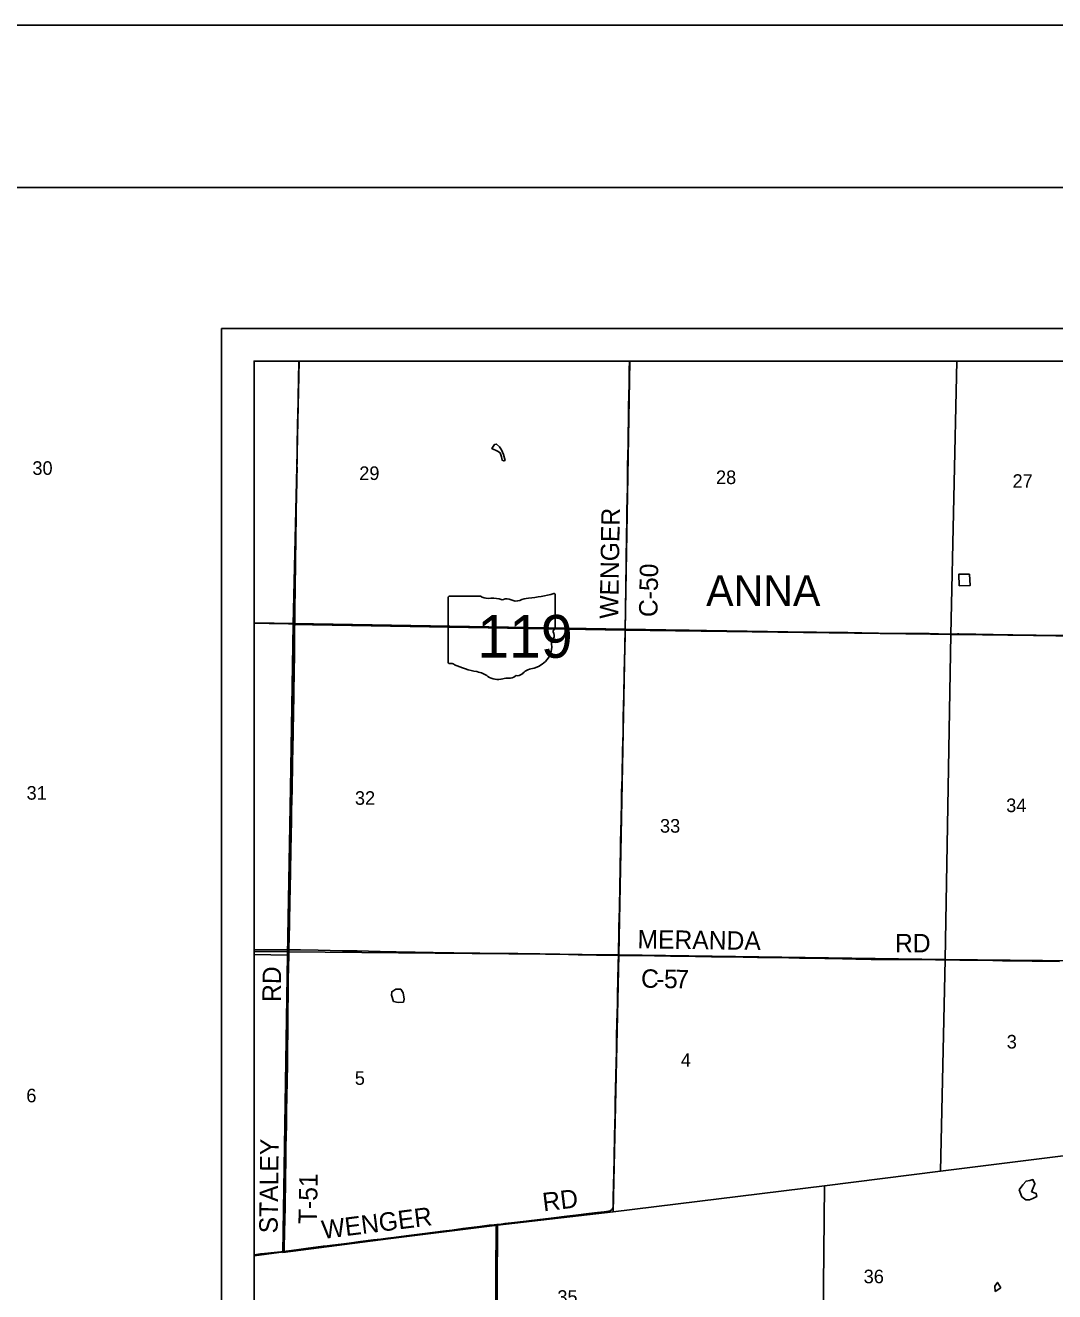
# Model space of a CAD drawing. Extents: x -784 to 1375, y -225 to 440.
# Drawn here: x 430.1 to 493.6, y 362 to 440 of the extents above; entities that cross this region are included whole.
import ezdxf

# ---------------------------------------------------------------- set-up
doc = ezdxf.new("R2010")
doc.units = 0
for name, color, linetype in [('GM_X_Corporation_Text', 7, 'Continuous'), ('GM_X_County_Road', 7, 'Continuous'), ('GM_X_County_Road_Text', 7, 'Continuous'), ('GM_X_Minor_Lake', 7, 'Continuous'), ('GM_X_Section', 7, 'Continuous'), ('GM_X_Section_Text', 7, 'Continuous'), ('GM_X_State_Location', 7, 'Continuous'), ('GM_X_State_Route', 7, 'Continuous'), ('GM_X_State_Shield', 7, 'Continuous'), ('GM_X_Township', 7, 'Continuous'), ('GM_X_Township_Road', 7, 'Continuous'), ('GM_X_Township_Road_Text', 7, 'Continuous'), ('SH_Border', 7, 'Continuous'), ('SH_Cut_Line', 7, 'Continuous'), ('SH_Data', 7, 'Continuous')]:
    doc.layers.add(name, color=color, linetype=linetype)

msp = doc.modelspace()

# ---------------------------------------------------------------- linework, layer by layer
at = {"layer": 'GM_X_County_Road'}
for points in [[(467.114, 402.781), (467.115, 402.882), (467.119, 403.76), (467.119, 404.034), (467.122, 404.171), (467.145, 405.264), (467.173, 407.054), (467.196, 408.546), (467.21, 409.503), (467.219, 410.075), (467.232, 410.87), (467.243, 411.492), (467.251, 411.989), (467.259, 412.834), (467.275, 413.543), (467.285, 414.164), (467.294, 414.947), (467.309, 415.544), (467.319, 416.501), (467.348, 417.881), (467.363, 418.751), (467.375, 419.309)], [(466.693, 382.69), (467.683, 382.675), (468.913, 382.652), (469.895, 382.64), (471.448, 382.616), (472.417, 382.602), (474.381, 382.57), (475.263, 382.557), (475.984, 382.551), (477.189, 382.528), (477.848, 382.522), (478.42, 382.514), (478.855, 382.508), (479.414, 382.498), (480.023, 382.487), (480.508, 382.482), (481.315, 382.457), (482.259, 382.439), (482.768, 382.436), (483.315, 382.43), (483.787, 382.43), (484.57, 382.433), (485.167, 382.432), (485.751, 382.426), (486.223, 382.42), (487.093, 382.412), (487.739, 382.402), (488.472, 382.387), (489.764, 382.373), (490.361, 382.361), (490.709, 382.355), (491.579, 382.346), (492.188, 382.339), (492.921, 382.332), (493.207, 382.328), (493.878, 382.312)]]:
    msp.add_lwpolyline(points, dxfattribs=at)
at = {"layer": 'GM_X_Minor_Lake'}
msp.add_line((489.877, 362.3), (489.902, 361.974), dxfattribs=at)
for points in [[(459.484, 413.84), (459.357, 414.024), (459.185, 414.2), (459.056, 414.179), (458.893, 413.916), (459.247, 413.752), (459.405, 413.651), (459.478, 413.4)], [(459.478, 413.4), (459.536, 413.202), (459.634, 413.155), (459.703, 413.192), (459.601, 413.55), (459.484, 413.84)], [(488.326, 406.186), (487.673, 406.187), (487.686, 405.469)], [(487.686, 405.469), (488.362, 405.48), (488.326, 406.186)], [(453.431, 380.37), (453.273, 380.609), (452.977, 380.605), (452.725, 380.449), (452.699, 380.245), (452.837, 379.85)], [(452.837, 379.85), (453.111, 379.784), (453.445, 379.81), (453.478, 379.992), (453.431, 380.37)], [(492.146, 368.115), (492.354, 368.619), (492.237, 368.871), (492.046, 368.822), (491.809, 368.782), (491.608, 368.551), (491.381, 368.23)], [(491.381, 368.23), (491.557, 367.817), (491.789, 367.631), (492.032, 367.633), (492.224, 367.705), (492.469, 367.829), (492.442, 368.019), (492.146, 368.115)], [(490.262, 362.199), (490.049, 362.532), (489.877, 362.3)], [(489.902, 361.974), (490.262, 362.199)]]:
    msp.add_lwpolyline(points, dxfattribs=at)
at = {"layer": 'GM_X_Section'}
for p, q in [((467.389, 419.309), (447.006, 419.309)), ((487.553, 419.309), (467.389, 419.309)), ((507.516, 419.309), (487.553, 419.309)), ((444.236, 403.181), (444.236, 382.934)), ((444.236, 382.934), (444.236, 364.18)), ((444.236, 364.18), (444.236, 354.38))]:
    msp.add_line(p, q, dxfattribs=at)
for points in [[(447.006, 419.309), (444.236, 419.309), (444.236, 403.181)], [(444.236, 403.181), (446.704, 403.137), (447.006, 419.309)], [(447.006, 419.309), (446.704, 403.137), (467.106, 402.786), (467.389, 419.309)], [(467.389, 419.309), (467.106, 402.786), (487.175, 402.456), (487.553, 419.309)], [(487.553, 419.309), (487.175, 402.456), (507.224, 402.301), (507.516, 419.309)], [(444.236, 382.934), (446.364, 382.916), (446.704, 403.137), (444.236, 403.181)], [(444.236, 364.18), (446.077, 364.411), (446.364, 382.916), (444.236, 382.934)], [(444.236, 354.38), (459.168, 354.279), (459.245, 366.065), (446.077, 364.411), (444.236, 364.18)]]:
    msp.add_lwpolyline(points, dxfattribs=at)
for points in [[(446.704, 403.137), (467.106, 402.786), (466.723, 382.718), (446.364, 382.916)], [(467.106, 402.786), (487.175, 402.456), (486.823, 382.433), (466.723, 382.718)], [(487.175, 402.456), (507.224, 402.301), (506.818, 382.234), (486.823, 382.433)], [(446.364, 382.916), (466.723, 382.718), (466.358, 366.879), (459.245, 366.065), (446.077, 364.411)], [(466.723, 382.718), (486.823, 382.433), (486.548, 369.394), (479.388, 368.483), (466.358, 366.879)], [(486.823, 382.433), (506.818, 382.234), (506.617, 371.896), (499.684, 371.026), (486.548, 369.394)], [(499.684, 371.026), (499.42, 354.13), (479.771, 354.211), (479.249, 354.244), (479.388, 368.483), (486.548, 369.394)], [(466.358, 366.879), (479.388, 368.483), (479.249, 354.244), (459.168, 354.279), (459.245, 366.065)]]:
    msp.add_lwpolyline(points, close=True, dxfattribs=at)
at = {"layer": 'GM_X_State_Route'}
for points in [[(444.236, 403.166), (444.292, 403.165), (445.162, 403.148), (445.933, 403.132), (446.367, 403.125), (446.609, 403.125), (446.745, 403.125), (447.771, 403.096), (448.703, 403.082), (449.56, 403.073), (450.679, 403.05), (451.473, 403.037), (452.43, 403.023), (454.593, 402.988), (456.196, 402.961), (457.637, 402.935), (458.296, 402.926), (459.463, 402.906), (461.663, 402.874), (462.396, 402.862), (463.751, 402.838), (464.558, 402.828), (466.559, 402.789), (467.114, 402.781), (468.137, 402.768), (471.057, 402.719), (472.213, 402.697), (474.151, 402.665), (476.189, 402.632), (477.915, 402.605)], [(477.915, 402.605), (478.9, 402.596), (479.658, 402.585), (480.428, 402.579), (480.838, 402.575), (481.695, 402.563), (482.727, 402.553), (484.155, 402.531), (485.843, 402.516), (486.418, 402.501), (487.127, 402.489)], [(487.127, 402.489), (487.581, 402.494), (487.667, 402.492)], [(487.667, 402.492), (489.792, 402.455), (490.867, 402.437)], [(490.867, 402.437), (490.996, 402.434), (491.754, 402.427), (492.087, 402.425)], [(492.087, 402.425), (492.167, 402.425), (492.437, 402.421), (493.682, 402.405), (494.114, 402.398), (495.239, 402.389), (495.282, 402.388), (495.555, 402.385), (495.682, 402.384)]]:
    msp.add_lwpolyline(points, dxfattribs=at)
at = {"layer": 'GM_X_State_Shield'}
for p, q in [((456.199, 404.746), (456.199, 400.744)), ((458.194, 404.815), (456.264, 404.815)), ((462.791, 402.821), (462.791, 404.914)), ((462.79, 402.821), (462.791, 402.821))]:
    msp.add_line(p, q, dxfattribs=at)
for centre, major_axis, start_param, end_param in [((456.274, 404.755), (0.0764, 0), 1.712693, 3.28349), ((458.654, 405.28), (0.741, 0), 4.042523, 4.731795), ((458.899, 402.568), (2.659, 0), 1.404758, 1.657858), ((459.503, 404.776), (0.214, 0), 3.836095, 5.185415), ((459.817, 404.313), (0.444, 0), 0.950623, 2.079405), ((460.39, 404.948), (0.534, 0), 4.081561, 5.145723), ((461.334, 403.593), (1.406, 0), 1.699011, 2.107814), ((460.442, 410.272), (6.99, 0), 4.814394, 5.042369), ((462.717, 404.923), (0.0734, 0), 6.141152, 7.989035), ((462.774, 402.667), (0.114, 0), 1.883978, 3.671073), ((462.712, 402.813), (0.0785, 0), 5.05454, 6.418171), ((460.834, 401.678), (1.748, 0), 5.101752, 6.440018), ((463.053, 401.944), (0.496, 0), 2.387724, 3.262537), ((462.051, 402.402), (0.682, 0), 5.934695, 6.695948), ((456.275, 400.735), (0.077, 0), 3.00124, 4.508301), ((456.287, 401.145), (0.588, 0), 4.665946, 4.897461), ((456.407, 400.513), (0.212, 0), 0.519207, 1.627899), ((459.084, 404.109), (5.048, 0), 4.195997, 4.488961), ((461.571, 399.62), (0.958, 0), 1.647645, 2.488434), ((457.579, 398.946), (1.579, 0), 0.823519, 1.323587), ((459.287, 400.493), (1.002, 0), 4.026481, 4.996735), ((459.866, 399.109), (0.824, 0), 1.495662, 1.94098), ((459.939, 400.193), (0.534, 0), 4.691044, 5.507374), ((460.422, 399.806), (0.15, 0), 1.147584, 2.315152), ((460.358, 400.356), (0.565, 0), 4.937069, 5.64225)]:
    msp.add_ellipse(centre, major_axis=major_axis, ratio=0.8, start_param=start_param, end_param=end_param, dxfattribs=at)
at = {"layer": 'GM_X_Township'}
msp.add_line((567.763, 419.309), (447.025, 419.309), dxfattribs=at)
for points in [[(447.025, 419.309), (444.236, 419.309), (444.236, 382.734)], [(444.236, 382.734), (446.293, 382.704), (446.474, 392.987), (446.652, 403.07), (446.855, 411.89), (447.025, 419.309)], [(447.025, 419.309), (446.855, 411.89), (446.652, 403.07), (467.059, 402.728), (492.276, 402.408), (492.603, 402.404), (493.649, 402.379), (495.222, 402.342), (497.28, 402.294), (498.869, 402.289), (499.79, 402.287), (508.769, 402.226), (510.045, 402.212), (511.496, 402.178), (514.371, 402.111), (537.416, 401.801), (552.453, 401.662), (567.523, 401.722), (567.763, 419.309)], [(459.121, 359.929), (459.158, 366.091), (446.019, 364.376), (446.293, 382.704), (446.474, 392.987), (446.652, 403.07), (467.059, 402.728), (492.276, 402.408), (492.603, 402.404), (493.649, 402.379)], [(444.236, 382.734), (444.236, 283.309), (458.267, 283.309)], [(458.267, 283.309), (458.263, 284.231), (458.296, 294.134), (458.336, 314.323), (458.289, 334.394), (458.283, 337.182), (458.257, 342.903), (458.257, 344.192), (458.276, 344.705), (458.316, 345.264), (458.426, 346.547), (458.496, 347.13), (458.717, 349.506), (458.868, 351.4), (458.971, 352.658), (459.085, 354.3), (459.121, 359.929), (459.158, 366.091), (446.019, 364.376), (446.293, 382.704), (444.236, 382.734)]]:
    msp.add_lwpolyline(points, dxfattribs=at)
at = {"layer": 'GM_X_Township_Road'}
for points in [[(446.872, 411.883), (446.879, 412.233), (446.884, 412.593), (446.882, 412.979), (446.888, 413.562), (446.896, 414.134), (446.899, 414.407), (446.91, 415.003), (446.923, 415.45), (446.933, 416.047), (446.951, 416.842), (446.965, 417.414), (446.973, 417.836), (446.993, 418.643), (447.004, 419.166), (447.006, 419.309)], [(446.745, 403.125), (446.746, 403.187), (446.751, 403.709), (446.758, 404.33), (446.766, 405.001), (446.781, 405.809), (446.784, 406.405), (446.798, 407.337), (446.808, 407.983), (446.822, 408.728), (446.832, 409.449), (446.839, 410.095), (446.853, 410.978), (446.872, 411.883)], [(446.578, 392.987), (446.588, 393.434), (446.599, 393.993), (446.607, 394.441), (446.613, 394.689), (446.624, 395.36), (446.644, 396.478), (446.665, 397.634), (446.681, 398.665), (446.694, 399.274), (446.704, 399.771), (446.712, 400.342), (446.72, 401.026), (446.726, 401.473), (446.733, 402.044), (446.734, 402.553), (446.738, 402.864), (446.745, 403.125)], [(466.693, 382.69), (466.7, 383.133), (466.713, 383.816), (466.722, 384.45), (466.748, 385.593), (466.774, 386.997), (466.796, 387.979), (466.808, 388.488), (466.818, 388.948), (466.828, 389.631), (466.845, 390.414), (466.857, 391.023), (466.88, 392.203), (466.888, 392.75), (466.901, 393.172), (466.916, 393.644), (466.924, 394.203), (466.938, 394.812), (466.949, 395.296), (466.962, 395.856), (466.974, 396.402), (466.982, 396.899), (466.99, 397.284), (467.009, 398.117), (467.023, 398.738), (467.053, 400.055), (467.07, 400.912), (467.089, 401.571), (467.107, 402.428), (467.114, 402.781)], [(446.38, 383.029), (446.384, 383.196), (446.395, 383.73), (446.413, 384.7), (446.445, 386.041), (446.46, 386.774), (446.483, 387.88), (446.505, 389.172), (446.521, 390.092), (446.537, 390.949), (446.55, 391.62), (446.576, 392.9), (446.578, 392.987)], [(444.236, 383.037), (444.99, 383.035), (445.711, 383.035), (446.27, 383.03), (446.38, 383.029)], [(446.242, 372.949), (446.245, 373.082), (446.262, 374.001), (446.284, 374.908), (446.285, 375.182), (446.296, 375.716), (446.296, 376.425), (446.302, 377.182), (446.311, 377.766), (446.318, 378.661), (446.322, 379.233), (446.333, 380.314), (446.339, 380.699), (446.345, 381.159), (446.358, 382.003), (446.371, 382.649), (446.38, 383.029)], [(446.38, 383.029), (447.091, 383.021), (448.184, 383.002), (448.918, 382.991), (449.688, 382.976), (450.583, 382.961), (451.291, 382.951), (452.012, 382.935), (452.994, 382.909), (453.677, 382.893), (454.162, 382.883), (454.572, 382.873), (455.267, 382.858), (456.15, 382.843), (456.547, 382.838), (456.994, 382.833), (457.591, 382.827), (458.15, 382.822), (459.02, 382.811), (460.487, 382.793), (461.842, 382.774), (463.072, 382.753), (463.607, 382.741), (464.203, 382.725), (464.998, 382.713), (465.346, 382.709), (465.905, 382.705), (466.489, 382.693), (466.564, 382.692), (466.693, 382.69)], [(459.189, 366.105), (459.464, 366.131), (459.698, 366.158), (460.105, 366.207), (461.007, 366.313), (461.846, 366.41), (462.549, 366.499), (463.511, 366.615), (464.065, 366.687), (464.868, 366.781), (465.399, 366.843), (465.818, 366.891), (466.077, 366.92), (466.148, 366.935), (466.203, 366.956), (466.244, 366.979), (466.281, 367.008), (466.311, 367.042), (466.335, 367.081), (466.354, 367.136), (466.366, 367.206), (466.371, 367.304), (466.375, 367.814), (466.382, 368.51), (466.401, 369.317), (466.419, 370.125), (466.432, 370.647), (466.444, 371.131), (466.452, 371.665), (466.462, 372.2), (466.483, 372.995), (466.5, 373.715), (466.512, 374.374), (466.537, 375.368), (466.551, 376.026), (466.564, 376.846), (466.582, 377.667), (466.602, 378.549), (466.626, 379.691), (466.638, 380.35), (466.654, 381.108), (466.683, 382.238), (466.693, 382.661), (466.693, 382.69)], [(446.091, 364.449), (446.094, 364.534), (446.098, 364.646), (446.121, 365.64), (446.135, 366.41), (446.145, 367.18), (446.156, 367.603), (446.172, 368.485), (446.184, 369.094), (446.196, 369.976), (446.198, 370.324), (446.203, 370.982), (446.21, 371.454), (446.227, 372.324), (446.242, 372.949)], [(448.75, 364.79), (449.069, 364.83), (449.6, 364.896), (450.105, 364.96), (450.795, 365.049), (451.597, 365.149), (452.04, 365.206), (452.484, 365.263), (452.854, 365.309), (453.607, 365.4), (454.592, 365.528), (455.875, 365.692), (456.442, 365.763), (457.107, 365.849), (458.155, 365.986), (458.734, 366.058), (459.031, 366.09), (459.189, 366.105)], [(459.122, 354.347), (459.133, 354.603), (459.139, 354.988), (459.143, 356.056), (459.148, 357.237), (459.152, 358.169), (459.154, 359.251), (459.16, 359.922), (459.163, 360.581), (459.167, 361.326), (459.167, 362.122), (459.171, 362.719), (459.175, 363.539), (459.176, 364.247), (459.178, 364.956), (459.177, 365.615), (459.185, 365.938), (459.189, 366.105)], [(444.236, 364.243), (444.382, 364.26), (444.629, 364.288), (444.888, 364.318), (445.469, 364.379), (446.091, 364.449)], [(446.091, 364.449), (446.21, 364.463), (446.863, 364.547), (447.418, 364.616), (447.579, 364.638)], [(447.579, 364.638), (448.49, 364.758), (448.75, 364.79)]]:
    msp.add_lwpolyline(points, dxfattribs=at)
at = {"layer": 'SH_Border'}
msp.add_lwpolyline([(30, 430), (670, 430), (670, 10), (30, 10)], close=True, dxfattribs=at)
at = {"layer": 'SH_Cut_Line'}
msp.add_lwpolyline([(0, 0), (680, 0), (680, 440), (0, 440)], close=True, dxfattribs=at)
at = {"layer": 'SH_Data'}
for p, q in [((442.236, 421.309), (582.236, 421.309)), ((442.236, 421.309), (442.236, 281.309)), ((444.236, 419.309), (444.236, 283.309)), ((444.236, 419.309), (580.236, 419.309))]:
    msp.add_line(p, q, dxfattribs=at)

# ---------------------------------------------------------------- texts
at = {"layer": 'GM_X_Corporation_Text'}
msp.add_text('ANNA', height=1.8939, rotation=0.00001, dxfattribs=at).set_placement((472.099, 404.223))
at = {"layer": 'GM_X_County_Road_Text'}
for s, height, rotation, p in [('WENGER', 1.1364, 89.04004, (466.67, 403.42)), ('C-50', 1.1364, 88.98492, (469.091, 403.526)), ('MERANDA', 1.1364, 359.18946, (467.86, 383.124)), ('RD', 1.1364, 0.00001, (483.733, 382.874)), ('C', 1.136, 358.13402, (468.068, 380.709)), ('5', 1.136, 359.4144, (469.495, 380.67)), ('7', 1.136, 359.5213, (470.197, 380.663)), ('-', 1.136, 359.06989, (469.021, 380.678))]:
    msp.add_text(s, height=height, rotation=rotation, dxfattribs=at).set_placement(p)
at = {"layer": 'GM_X_Section_Text'}
for s, height, p in [('30', 0.8371, (430.578, 412.299)), ('29', 0.8371, (450.72, 411.982)), ('28', 0.8371, (472.703, 411.732)), ('27', 0.8371, (490.978, 411.499)), ('31', 0.8371, (430.22, 392.282)), ('32', 0.8371, (450.453, 391.966)), ('34', 0.8371, (490.587, 391.516)), ('33', 0.8371, (469.253, 390.249)), ('3', 0.837, (490.62, 376.949)), ('4', 0.837, (470.537, 375.822)), ('5', 0.837, (450.445, 374.71)), ('6', 0.837, (430.203, 373.632)), ('36', 0.8371, (481.803, 362.482)), ('35', 0.8371, (462.928, 361.216))]:
    msp.add_text(s, height=height, rotation=0.00001, dxfattribs=at).set_placement(p)
at = {"layer": 'GM_X_State_Location'}
msp.add_text('119', height=0.00379, rotation=0.00001, dxfattribs=at).set_placement((458.083, 402.203))
for s in ['s', 'r']:
    msp.add_text(s, height=0.00379, dxfattribs=at).set_placement((459.421, 402.479))
at = {"layer": 'GM_X_State_Shield'}
msp.add_text('119', height=2.6367, dxfattribs=at).set_placement((457.988, 401.026))
at = {"layer": 'GM_X_Township_Road_Text'}
for s, rotation, p in [('RD', 89.50748, (445.887, 379.812)), ('STALEY', 89.28886, (445.686, 365.555)), ('T-51', 88.95264, (448.106, 366.123)), ('RD', 6.94108, (462.079, 366.908)), ('WENGER', 7.20335, (448.476, 365.208))]:
    msp.add_text(s, height=1.1364, rotation=rotation, dxfattribs=at).set_placement(p)

doc.saveas('drawing.dxf')
